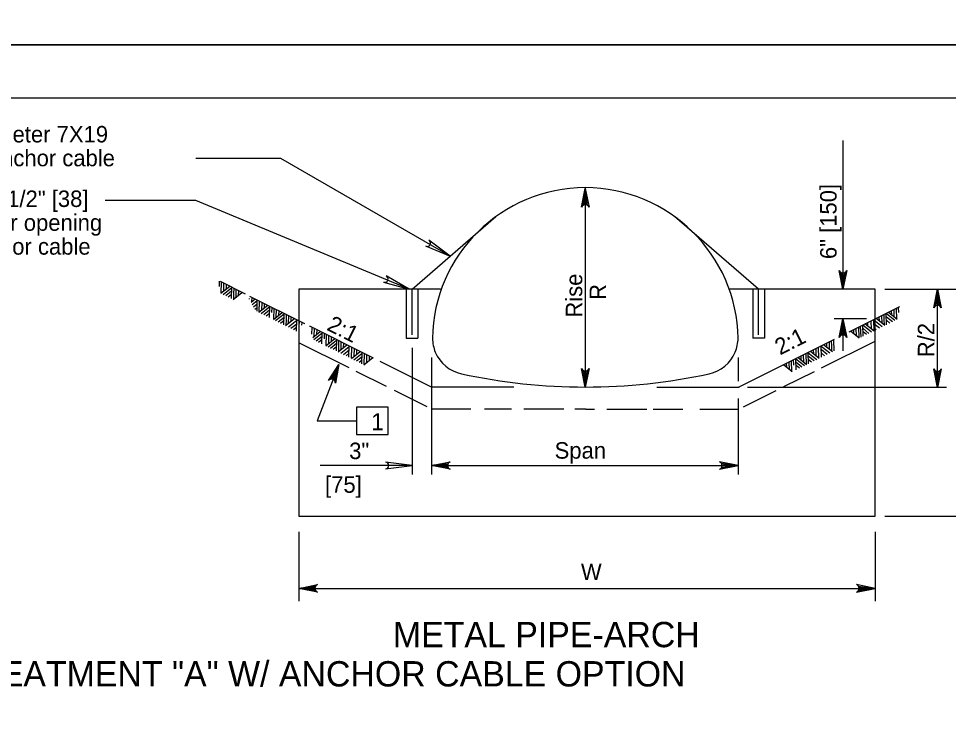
# Model space of a CAD drawing. Extents: x 1083.1 to 1117.1, y 675.4 to 741.4.
# Drawn here: x 1103.72 to 1112.53, y 712.98 to 719.6 of the extents above; entities that cross this region are included whole.
import ezdxf

# ---------------------------------------------------------------- set-up
doc = ezdxf.new("R2010")
doc.units = 0
doc.layers.add('Level 1', color=7, linetype='Continuous')
doc.layers.add('Level 44', color=7, linetype='Continuous')

msp = doc.modelspace()

# ---------------------------------------------------------------- linework, layer by layer
at = {"layer": 'Level 1'}
for p, q in [((1111.5334, 718.4475), (1111.5334, 717.04)), ((1106.2082, 718.2766), (1105.404, 718.2766)), ((1107.8111, 717.3514), (1106.2082, 718.2766)), ((1109.0674, 717.8308), (1109.0922, 717.993)), ((1109.0778, 717.837), (1109.0922, 717.993)), ((1109.0922, 718.0023), (1109.0922, 716.663)), ((1109.0922, 717.8398), (1109.0922, 717.993)), ((1109.1036, 717.8382), (1109.0922, 717.993)), ((1109.1147, 717.8328), (1109.0922, 717.993)), ((1105.4027, 717.8813), (1104.5439, 717.8813)), ((1107.424, 717.04), (1105.4027, 717.8813)), ((1107.4509, 717.04), (1108.2464, 717.7278)), ((1110.7336, 717.04), (1109.9381, 717.7278)), ((1111.511, 717.2002), (1111.5334, 717.04)), ((1111.5221, 717.1948), (1111.5334, 717.04)), ((1111.5582, 717.2022), (1111.5334, 717.04)), ((1111.5478, 717.196), (1111.5334, 717.04)), ((1111.5334, 717.1932), (1111.5334, 717.04)), ((1105.6263, 717.066), (1105.6279, 717.1156)), ((1105.8725, 716.9933), (1105.6358, 717.1117)), ((1105.6408, 717.0011), (1105.7242, 717.0677)), ((1105.6435, 717.0031), (1105.6465, 717.1063)), ((1105.6675, 717.0223), (1105.6698, 717.0946)), ((1105.6927, 717.0422), (1105.694, 717.0826)), ((1105.7403, 716.9513), (1105.7435, 717.0578)), ((1105.6622, 716.9903), (1105.7429, 717.0548)), ((1105.6859, 716.9785), (1105.7423, 717.0239)), ((1105.7088, 716.9671), (1105.7414, 716.9934)), ((1105.7568, 716.9431), (1105.8401, 717.0096)), ((1105.762, 716.9472), (1105.7633, 716.9976)), ((1105.7633, 716.9976), (1105.765, 717.0471)), ((1105.7843, 716.9649), (1105.7862, 717.0365)), ((1105.8083, 716.9842), (1105.8097, 717.0247)), ((1106.4357, 716.7117), (1105.9158, 716.9717)), ((1106.3772, 717.04), (1106.3772, 714.8872)), ((1107.7202, 717.04), (1106.3772, 717.04)), ((1107.396, 717.04), (1107.396, 716.5767)), ((1107.4509, 716.6067), (1107.4509, 717.04)), ((1107.5058, 717.04), (1107.5058, 716.5767)), ((1111.8389, 717.04), (1110.4556, 717.04)), ((1110.6787, 717.04), (1110.6787, 716.5767)), ((1110.7336, 716.6067), (1110.7336, 717.04)), ((1110.7885, 717.04), (1110.7885, 716.5767)), ((1111.8389, 714.8872), (1111.8389, 717.04)), ((1111.9292, 717.04), (1112.9574, 717.04)), ((1112.4038, 716.8779), (1112.4286, 717.04)), ((1112.4143, 716.884), (1112.4286, 717.04)), ((1112.4286, 716.8868), (1112.4286, 717.04)), ((1112.4399, 716.8852), (1112.4286, 717.04)), ((1112.451, 716.8797), (1112.4286, 717.04)), ((1112.4295, 716.4114), (1112.4295, 717.0371)), ((1105.9114, 716.9443), (1105.9116, 716.9498)), ((1105.9266, 716.9161), (1105.9652, 716.9469)), ((1105.934, 716.9227), (1105.9355, 716.9619)), ((1105.9382, 716.8942), (1105.9852, 716.9317)), ((1105.9503, 716.872), (1105.9844, 716.8993)), ((1105.9827, 716.8302), (1105.9854, 716.9369)), ((1106.0009, 716.821), (1106.0844, 716.8877)), ((1106.0037, 716.823), (1106.0066, 716.9263)), ((1106.0277, 716.8422), (1106.03, 716.9146)), ((1106.0528, 716.8623), (1106.0542, 716.9025)), ((1112.4478, 716.9413), (1112.4476, 716.9468)), ((1105.9626, 716.849), (1105.9835, 716.866)), ((1106.0224, 716.8102), (1106.1031, 716.8747)), ((1106.0461, 716.7984), (1106.1024, 716.8438)), ((1106.069, 716.787), (1106.1016, 716.8133)), ((1106.1004, 716.7713), (1106.1036, 716.8778)), ((1106.1235, 716.8175), (1106.1251, 716.8671)), ((1106.138, 716.7525), (1106.2213, 716.8193)), ((1106.1407, 716.7545), (1106.1436, 716.8578)), ((1106.1593, 716.7418), (1106.24, 716.8062)), ((1106.1646, 716.7737), (1106.1669, 716.8461)), ((1106.1898, 716.7937), (1106.1911, 716.8341)), ((1106.2373, 716.7028), (1106.2406, 716.8093)), ((1106.2604, 716.749), (1106.2621, 716.7986)), ((1111.5927, 716.6361), (1112.0718, 716.8757)), ((1111.9241, 716.749), (1111.9224, 716.7986)), ((1111.9472, 716.7028), (1111.9439, 716.8093)), ((1112.0251, 716.7418), (1111.9445, 716.8062)), ((1112.0465, 716.7525), (1111.9632, 716.8193)), ((1111.9947, 716.7937), (1111.9933, 716.8341)), ((1112.0198, 716.7737), (1112.0175, 716.8461)), ((1112.0438, 716.7545), (1112.0408, 716.8578)), ((1112.061, 716.8175), (1112.0594, 716.8671)), ((1106.183, 716.73), (1106.2393, 716.7753)), ((1106.2059, 716.7186), (1106.2385, 716.7448)), ((1106.2539, 716.6946), (1106.3372, 716.761)), ((1106.2591, 716.6988), (1106.2604, 716.749)), ((1106.2798, 716.6817), (1106.3593, 716.7448)), ((1106.2814, 716.7164), (1106.2832, 716.788)), ((1106.3045, 716.6693), (1106.3585, 716.7124)), ((1106.3054, 716.7357), (1106.3069, 716.7762)), ((1106.3565, 716.6432), (1106.3595, 716.7498)), ((1106.383, 716.688), (1106.3845, 716.7373)), ((1106.4087, 716.6996), (1106.4095, 716.7249)), ((1106.4325, 716.7103), (1106.4326, 716.7134)), ((1111.7557, 716.7592), (1111.4502, 716.7592)), ((1111.5087, 716.5971), (1111.5334, 716.7592)), ((1111.519, 716.6032), (1111.5334, 716.7592)), ((1111.5334, 716.7592), (1111.5334, 716.4539)), ((1111.5334, 716.606), (1111.5334, 716.7592)), ((1111.5448, 716.6044), (1111.5334, 716.7592)), ((1111.5558, 716.5989), (1111.5334, 716.7592)), ((1111.828, 716.641), (1111.7416, 716.7102)), ((1111.7689, 716.6883), (1111.7678, 716.7213)), ((1111.8023, 716.6616), (1111.8, 716.7373)), ((1111.8279, 716.6432), (1111.8249, 716.7498)), ((1111.9047, 716.6817), (1111.8251, 716.7448)), ((1111.88, 716.6693), (1111.8259, 716.7124)), ((1111.9306, 716.6946), (1111.8473, 716.761)), ((1111.8791, 716.7357), (1111.8776, 716.7762)), ((1111.9031, 716.7164), (1111.9012, 716.788)), ((1111.9254, 716.6988), (1111.9241, 716.749)), ((1112.0014, 716.73), (1111.9452, 716.7753)), ((1111.9786, 716.7186), (1111.946, 716.7448)), ((1106.3288, 716.6571), (1106.3575, 716.6801)), ((1107.0876, 716.3858), (1106.4817, 716.6888)), ((1106.4825, 716.6859), (1106.4826, 716.6883)), ((1106.5018, 716.6141), (1106.5037, 716.6777)), ((1106.5104, 716.5824), (1106.5815, 716.6392)), ((1106.5196, 716.5617), (1106.6002, 716.6262)), ((1106.5248, 716.5937), (1106.5271, 716.6661)), ((1106.5499, 716.6137), (1106.5512, 716.654)), ((1106.5975, 716.5228), (1106.6007, 716.6292)), ((1106.6206, 716.569), (1106.6222, 716.6185)), ((1109.0922, 716.663), (1109.0922, 716.1123)), ((1111.688, 716.575), (1111.6047, 716.6417)), ((1111.6362, 716.6162), (1111.6347, 716.6565)), ((1111.6612, 716.5961), (1111.659, 716.6685)), ((1111.6853, 716.577), (1111.6823, 716.6803)), ((1111.7043, 716.5836), (1111.7009, 716.6895)), ((1111.7256, 716.5938), (1111.7224, 716.7002)), ((1111.8035, 716.6327), (1111.7229, 716.6972)), ((1111.7798, 716.6208), (1111.7236, 716.6662)), ((1111.757, 716.6094), (1111.7244, 716.6358)), ((1111.8484, 716.6535), (1111.8272, 716.6706)), ((1106.8547, 716.2938), (1106.3772, 716.5325)), ((1106.5432, 716.5499), (1106.5995, 716.5952)), ((1106.5661, 716.5385), (1106.5987, 716.5648)), ((1106.6351, 716.504), (1106.7184, 716.5707)), ((1106.6377, 716.506), (1106.6408, 716.6092)), ((1106.6565, 716.4932), (1106.7371, 716.5577)), ((1106.6618, 716.5252), (1106.6641, 716.5975)), ((1106.6868, 716.5453), (1106.6882, 716.5856)), ((1106.7344, 716.4543), (1106.7377, 716.5608)), ((1106.7575, 716.5005), (1106.7592, 716.5501)), ((1106.7785, 716.4678), (1106.7803, 716.5395)), ((1106.8025, 716.4871), (1106.804, 716.5277)), ((1107.396, 716.5767), (1107.5058, 716.5767)), ((1110.5449, 716.1123), (1111.4546, 716.5672)), ((1110.7885, 716.5767), (1110.6787, 716.5767)), ((1111.3297, 716.2938), (1111.8389, 716.5483)), ((1111.382, 716.4871), (1111.3805, 716.5277)), ((1111.406, 716.4678), (1111.4042, 716.5395)), ((1111.427, 716.5005), (1111.4253, 716.5501)), ((1111.45, 716.4543), (1111.4468, 716.5608)), ((1106.6801, 716.4814), (1106.7364, 716.5268)), ((1106.703, 716.47), (1106.7356, 716.4963)), ((1106.7511, 716.446), (1106.8343, 716.5125)), ((1106.7562, 716.4502), (1106.7575, 716.5005)), ((1106.7769, 716.4332), (1106.8564, 716.4963)), ((1106.8016, 716.4207), (1106.8557, 716.4638)), ((1106.8536, 716.3947), (1106.8566, 716.5013)), ((1106.8762, 716.3834), (1106.9594, 716.4498)), ((1106.8785, 716.3853), (1106.8816, 716.4888)), ((1106.9043, 716.406), (1106.9066, 716.4763)), ((1106.9282, 716.4257), (1106.9297, 716.4648)), ((1106.9769, 716.3331), (1106.9797, 716.4398)), ((1107.4509, 716.4827), (1107.4509, 715.2847)), ((1111.2076, 716.3331), (1111.2048, 716.4398)), ((1111.3083, 716.3834), (1111.2251, 716.4498)), ((1111.2563, 716.4257), (1111.2548, 716.4648)), ((1111.2802, 716.406), (1111.2779, 716.4763)), ((1111.3059, 716.3853), (1111.3028, 716.4888)), ((1111.3308, 716.3947), (1111.3278, 716.5013)), ((1111.4076, 716.4332), (1111.328, 716.4963)), ((1111.3829, 716.4207), (1111.3287, 716.4638)), ((1111.4334, 716.446), (1111.3502, 716.5125)), ((1111.4283, 716.4502), (1111.427, 716.5005)), ((1106.8261, 716.4086), (1106.8546, 716.4316)), ((1106.9001, 716.3715), (1106.9794, 716.4347)), ((1106.9248, 716.3592), (1106.9787, 716.4023)), ((1106.9501, 716.3465), (1106.9778, 716.3689)), ((1106.9952, 716.3239), (1107.0786, 716.3907)), ((1106.9979, 716.3259), (1107.0008, 716.4293)), ((1107.022, 716.3452), (1107.0242, 716.4176)), ((1107.047, 716.3652), (1107.0483, 716.4055)), ((1107.6349, 716.1123), (1107.1482, 716.3556)), ((1107.6349, 716.3908), (1107.6349, 715.2847)), ((1110.5409, 716.3908), (1110.5409, 716.1691)), ((1111.0497, 716.2575), (1111.0467, 716.3607)), ((1111.0668, 716.3204), (1111.0652, 716.37)), ((1111.0899, 716.2743), (1111.0867, 716.3807)), ((1111.1678, 716.3132), (1111.0873, 716.3777)), ((1111.1892, 716.3239), (1111.1058, 716.3907)), ((1111.1374, 716.3652), (1111.1361, 716.4055)), ((1111.1625, 716.3452), (1111.1602, 716.4176)), ((1111.1866, 716.3259), (1111.1837, 716.4293)), ((1111.2843, 716.3715), (1111.2051, 716.4347)), ((1111.2597, 716.3592), (1111.2058, 716.4023)), ((1111.2344, 716.3465), (1111.2068, 716.3689)), ((1111.3584, 716.4086), (1111.3298, 716.4316)), ((1112.4295, 716.1092), (1112.4295, 716.4114)), ((1106.7567, 716.3263), (1106.5509, 715.7918)), ((1106.6749, 716.1842), (1106.7567, 716.3263)), ((1106.6868, 716.1861), (1106.7567, 716.3263)), ((1106.7013, 716.1836), (1106.7567, 716.3263)), ((1106.7113, 716.178), (1106.7567, 716.3263)), ((1106.7196, 716.1689), (1106.7567, 716.3263)), ((1109.0698, 716.2725), (1109.0922, 716.1123)), ((1109.0809, 716.2671), (1109.0922, 716.1123)), ((1109.117, 716.2743), (1109.0922, 716.1123)), ((1109.1067, 716.2682), (1109.0922, 716.1123)), ((1109.0922, 716.2654), (1109.0922, 716.1123)), ((1111.0523, 716.2555), (1110.9689, 716.3222)), ((1111.0005, 716.2967), (1110.9991, 716.337)), ((1111.0256, 716.2767), (1111.0233, 716.349)), ((1111.1441, 716.3013), (1111.0879, 716.3467)), ((1111.1212, 716.29), (1111.0887, 716.3162)), ((1112.4071, 716.2695), (1112.4295, 716.1092)), ((1112.4182, 716.2641), (1112.4295, 716.1092)), ((1112.4543, 716.2714), (1112.4295, 716.1092)), ((1112.4438, 716.2652), (1112.4295, 716.1092)), ((1107.2107, 716.1159), (1106.9215, 716.2605)), ((1110.9737, 716.1159), (1111.263, 716.2605)), ((1112.4295, 716.2624), (1112.4295, 716.1092)), ((1108.4154, 716.1123), (1107.6349, 716.1123)), ((1109.7691, 716.1123), (1110.5496, 716.1123)), ((1110.3017, 716.1123), (1110.4576, 716.1123)), ((1110.6282, 716.1123), (1112.5133, 716.1123)), ((1107.593, 715.9249), (1107.2852, 716.0787)), ((1110.5409, 716.0026), (1110.5409, 715.2847)), ((1110.5914, 715.9249), (1110.8992, 716.0787)), ((1106.9251, 715.9227), (1106.9251, 715.661)), ((1107.2239, 715.9227), (1106.9251, 715.9227)), ((1107.2239, 715.661), (1107.2239, 715.9227)), ((1108.0068, 715.904), (1107.6349, 715.904)), ((1108.3946, 715.904), (1108.1387, 715.904)), ((1108.8883, 715.904), (1108.5092, 715.904)), ((1109.0986, 715.904), (1108.9939, 715.904)), ((1109.0986, 715.904), (1109.1788, 715.904)), ((1109.2962, 715.904), (1109.6753, 715.904)), ((1109.7346, 715.904), (1110.0165, 715.904)), ((1110.1778, 715.904), (1110.5409, 715.904)), ((1106.5509, 715.7918), (1106.9251, 715.7918)), ((1106.9251, 715.661), (1107.2239, 715.661)), ((1107.7952, 715.3904), (1107.6349, 715.368)), ((1110.3807, 715.3904), (1110.5409, 715.368)), ((1107.4509, 715.368), (1106.5798, 715.368)), ((1107.7897, 715.3793), (1107.6349, 715.368)), ((1107.6349, 715.368), (1109.431, 715.368)), ((1107.7881, 715.368), (1107.6349, 715.368)), ((1107.7909, 715.3536), (1107.6349, 715.368)), ((1107.7971, 715.3433), (1107.6349, 715.368)), ((1109.431, 715.368), (1110.5409, 715.368)), ((1110.3787, 715.3433), (1110.5409, 715.368)), ((1110.3849, 715.3536), (1110.5409, 715.368)), ((1110.3861, 715.3793), (1110.5409, 715.368)), ((1110.3877, 715.368), (1110.5409, 715.368)), ((1106.3772, 714.8872), (1111.8389, 714.8872)), ((1111.9292, 714.8872), (1112.9574, 714.8872)), ((1106.3772, 714.7397), (1106.3772, 714.0835)), ((1111.8389, 714.7397), (1111.8389, 714.0835)), ((1106.5374, 714.2263), (1106.3772, 714.2039)), ((1106.532, 714.2152), (1106.3772, 714.2039)), ((1106.5303, 714.2039), (1106.3772, 714.2039)), ((1106.5332, 714.1895), (1106.3772, 714.2039)), ((1106.5393, 714.1792), (1106.3772, 714.2039)), ((1106.3772, 714.2039), (1109.2678, 714.2039)), ((1109.2678, 714.2039), (1111.8389, 714.2039)), ((1111.6768, 714.1792), (1111.8389, 714.2039)), ((1111.6787, 714.2263), (1111.8389, 714.2039)), ((1111.6829, 714.1895), (1111.8389, 714.2039)), ((1111.6842, 714.2152), (1111.8389, 714.2039)), ((1111.6857, 714.2039), (1111.8389, 714.2039))]:
    msp.add_line(p, q, dxfattribs=at)
for points in [[(1083.1264, 719.3541), (1117.1264, 719.3541), (1117.1264, 741.3541), (1083.1264, 741.3541)], [(1083.1264, 697.3541), (1117.1264, 697.3541), (1117.1264, 719.3541), (1083.1264, 719.3541)], [(1083.1264, 697.3541), (1117.1264, 697.3541), (1117.1264, 719.3541), (1083.1264, 719.3541)], [(1085.1264, 718.8541), (1116.6264, 718.8541), (1116.6264, 697.8541), (1085.1264, 697.8541)]]:
    msp.add_lwpolyline(points, close=True, dxfattribs=at)
for points in [[(1109.0568, 717.816), (1109.0922, 717.993), (1109.1277, 717.816)], [(1111.5688, 717.217), (1111.5334, 717.04), (1111.498, 717.217)], [(1112.3932, 716.863), (1112.4286, 717.04), (1112.464, 716.863)], [(1111.498, 716.5822), (1111.5334, 716.7592), (1111.5688, 716.5822)], [(1106.6596, 716.1741), (1106.7567, 716.3263), (1106.7257, 716.1486)], [(1109.1277, 716.2892), (1109.0922, 716.1123), (1109.0568, 716.2892)], [(1112.4648, 716.2862), (1112.4295, 716.1092), (1112.3941, 716.2862)], [(1107.8119, 715.3326), (1107.6349, 715.368), (1107.8119, 715.4034)], [(1110.3639, 715.3326), (1110.5409, 715.368), (1110.3639, 715.4034)], [(1106.5542, 714.1685), (1106.3772, 714.2039), (1106.5542, 714.2393)], [(1111.6619, 714.1685), (1111.8389, 714.2039), (1111.6619, 714.2393)]]:
    msp.add_lwpolyline(points, dxfattribs=at)
for centre, start, end in [((1109.0923, 717.8017), 22.08782, 157.91395), ((1111.5334, 717.2313), 202.08782, 337.91395), ((1112.4286, 716.8487), 22.08782, 157.91395), ((1111.5335, 716.5679), 22.08782, 157.91395), ((1109.0922, 716.3035), 202.08782, 337.91395), ((1112.4294, 716.3005), 202.08782, 337.91395), ((1106.6875, 716.148), 0.89029, 136.71641), ((1107.8262, 715.368), 112.08782, 247.91395), ((1110.3496, 715.368), 292.08605, 67.91218), ((1106.5685, 714.204), 112.08782, 247.91395), ((1111.6476, 714.204), 292.08605, 67.91218)]:
    msp.add_arc(centre, 0.0382, start, end, dxfattribs=at)
for centre, major_axis, start_param, end_param in [((1109.0966, 716.5493), (-1.4532, 0), 4.71537, 6.266539), ((1109.0879, 716.5493), (1.4532, 0), 0.016646, 1.567816), ((1108.091, 716.5981), (-0.448, 0), 0.055055, 0.354919), ((1110.0934, 716.5981), (0.448, 0), 5.928267, 6.22813), ((1107.9925, 716.5803), (-0.3498, 0), 0.40505, 1.357703), ((1110.1919, 716.5803), (0.3498, 0), 4.925482, 5.878135), ((1109.0812, 721.5306), (5.419, 0), 4.496144, 4.714418), ((1109.1032, 721.5306), (-5.419, 0), 1.568767, 1.787041)]:
    msp.add_ellipse(centre, major_axis=major_axis, ratio=0.999895, start_param=start_param, end_param=end_param, dxfattribs=at)
at = {"layer": 'Level 44'}
for p, q in [((1107.8111, 717.3514), (1107.6102, 717.5035)), ((1107.5789, 717.4493), (1107.8111, 717.3514)), ((1107.424, 717.04), (1107.2052, 717.1649)), ((1107.1812, 717.1073), (1107.424, 717.04)), ((1107.4509, 715.368), (1107.2009, 715.3992)), ((1107.2009, 715.3367), (1107.4509, 715.368))]:
    msp.add_line(p, q, dxfattribs=at)
for centre, start, end in [((1107.5946, 717.4764), 240.00616, 60.00616), ((1107.1932, 717.1361), 247.40077, 67.40077), ((1107.2009, 715.368), 270, 90)]:
    msp.add_arc(centre, 0.0312, start, end, dxfattribs=at)

# ---------------------------------------------------------------- texts
at = {"layer": 'Level 1'}
for s, height, p in [('3/8" [10] diameter 7X19', 0.156, (1102.387, 718.4304)), ('galvanized anchor cable', 0.156, (1102.387, 718.2044)), ('1 1/2" [38]', 0.156, (1103.4423, 717.8187)), ('diameter opening', 0.156, (1102.9037, 717.5927)), ('for anchor cable', 0.156, (1102.9101, 717.3667)), ('1', 0.16, (1107.0639, 715.7034)), ('3"', 0.156, (1106.8558, 715.4293)), ('Span', 0.156, (1108.8019, 715.4333)), ('[75]', 0.156, (1106.6271, 715.1101)), ('W', 0.156, (1109.051, 714.2832)), ('METAL PIPE-ARCH', 0.24, (1107.2698, 713.6464)), ('PLASTIC & METAL PIPE END TREATMENT "A" W/ ANCHOR CABLE OPTION', 0.24, (1098.6507, 713.2742))]:
    msp.add_text(s, height=height, dxfattribs=at).set_placement(p)
for s, rotation, p in [('6" [150]', 90, (1111.473, 717.3248)), ('Rise', 90, (1109.0635, 716.77)), ('R', 90, (1109.2895, 716.9376)), ('2:1', 333.43737, (1106.6344, 716.6563)), ('R/2', 90, (1112.3984, 716.3949)), ('2:1', 26.56263, (1110.9374, 716.411))]:
    msp.add_text(s, height=0.156, rotation=rotation, dxfattribs=at).set_placement(p)

doc.saveas('drawing.dxf')
